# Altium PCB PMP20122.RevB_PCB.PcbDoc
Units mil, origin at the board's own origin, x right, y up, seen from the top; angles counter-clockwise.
Board outline 2960 x 1600 mil, 2 copper layers (Top Layer, Bottom Layer), stack 62 mil thick; 29 components, 14 nets, 63 pads, 28 vias.
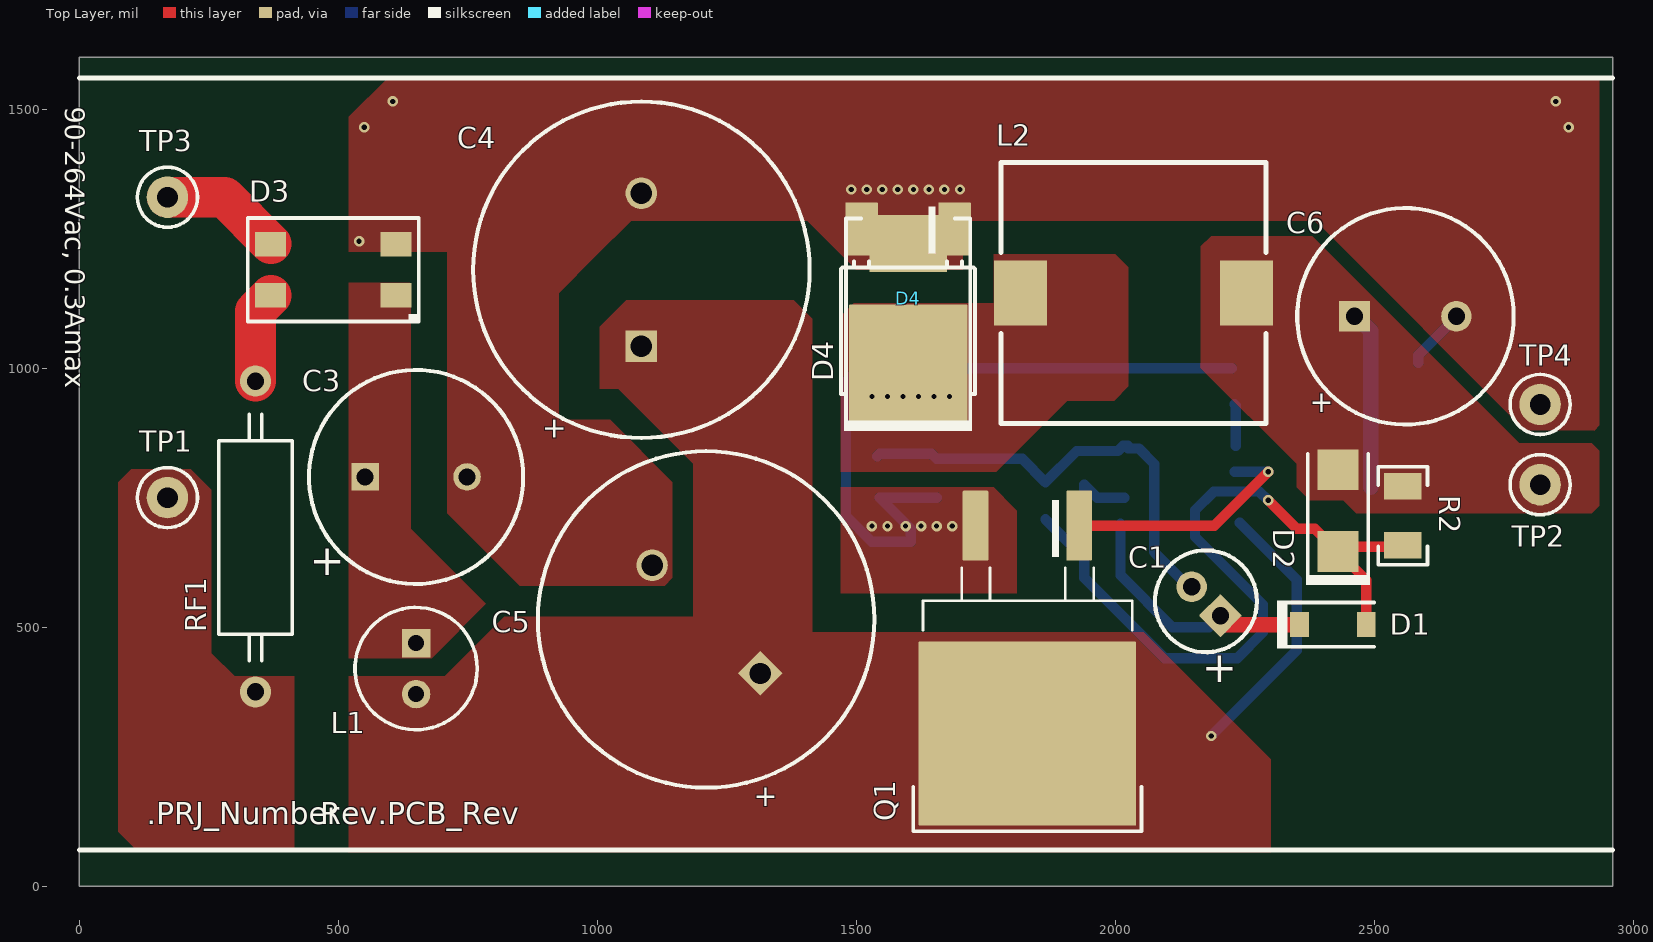
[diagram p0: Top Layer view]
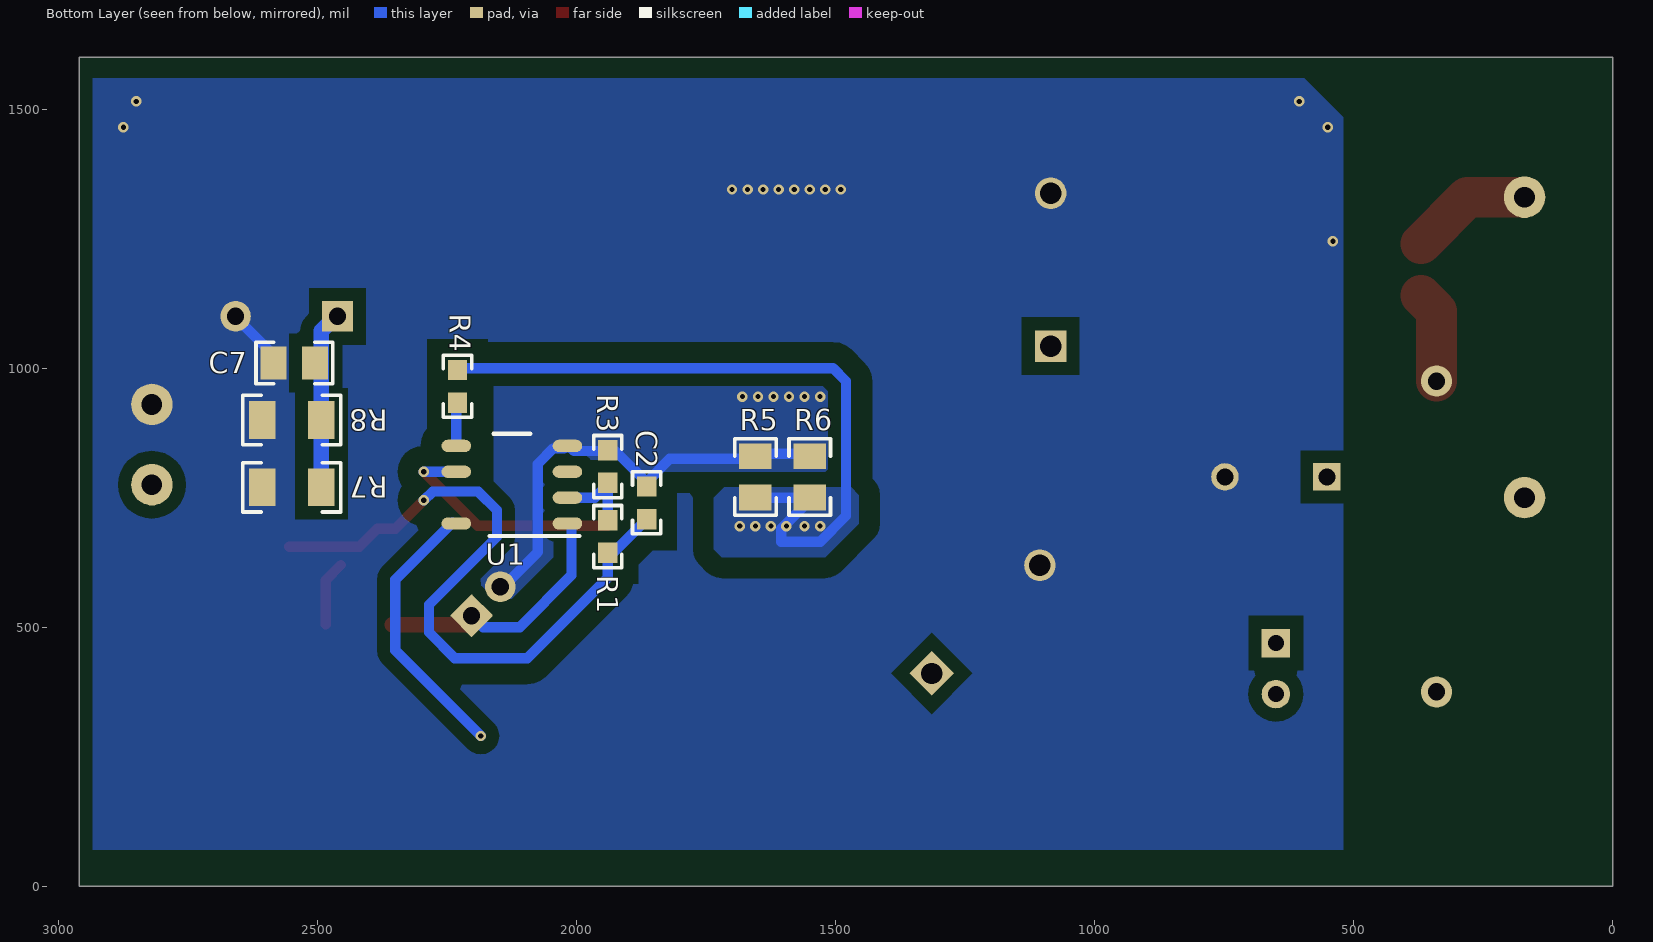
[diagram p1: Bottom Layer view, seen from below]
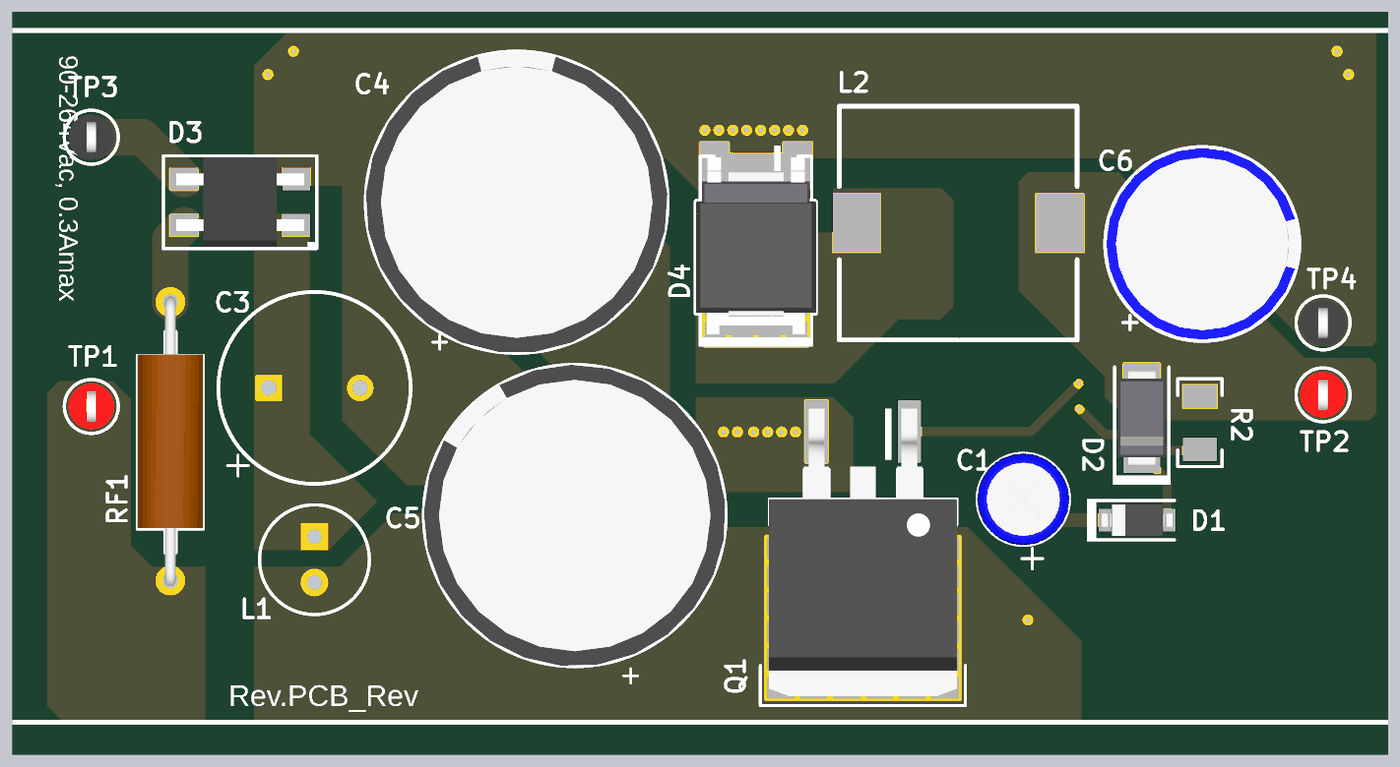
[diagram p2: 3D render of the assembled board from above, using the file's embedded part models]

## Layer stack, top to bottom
Top Solder: solder mask 0.4, Solder Resist, Dk 3.5
Top Layer: signal copper 1.4
Dielectric1: core 59.2, FR-4, Dk 4.8
Bottom Layer: signal copper 1.4
Bottom Solder: solder mask 0.4, Solder Resist, Dk 3.5

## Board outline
0,0 2960,0 2960,1600 0,1600

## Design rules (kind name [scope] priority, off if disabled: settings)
AcuteAngle [All] p1: minimum=4.50000000000000E+0001 checktracksonly=FALSE
AssemblyTestPointUsage [All] p1: valid=2
BoardOutlineClearance BoardOutlineClearance_MountingHoles [OnCopper and InComponentClass('Mounting Holes')] p1: gap=40
BoardOutlineClearance BoardOutlineClearance_Poly [OnCopper and IsPoly] p2: gap=25
BoardOutlineClearance [OnCopper and Not InComponentClass('Logo') and not InComponentClass('FiducialMark') and not InRegion(1000,500,4000,800) and not InPoly] p3: gap=75
Clearance Clearance_5 [InNetClass('SW') vs InNet('GND')] p1: gap=40
Clearance Clearance_4 [InNamedPolygon('TOP_LAYER_GND_P000')] p2: gap=60
Clearance Clearance_3 [InNamedPolygon('TOP_LAYER_GND_P000')] p3: gap=60
Clearance Clearance_2 [InNamedPolygon('TOP_LAYER_GND_P000')] p4: gap=10
Clearance Clearance_1 [InNetClass('HV') vs InNetClass('SW')] p5: gap=40
Clearance Clearance_Keepouts [((IsTrack Or IsArc) And Not InPoly) And IsFree and IsKeepOut vs ((IsTrack Or IsArc) And Not InPoly) And IsFree and IsKeepOut] p6: gap=0
Clearance Clearance_Poly [InPolygon] p7: gap=25
Clearance [All] p8: gap=7.87
ComponentClearance ComponentClearance_MountingHoles_FiducialMarks [InComponentClass('Mounting Holes') vs InComponentClass('FiducialMark')] p1: gap=50 collisioncheckmode=3 verticalgap=10 showdistances=FALSE
ComponentClearance ComponentClearance_Shunt [InComponentClass('Header') vs InComponentClass('Shunt')] p2: gap=0 collisioncheckmode=3 verticalgap=0 showdistances=FALSE
ComponentClearance ComponentClearance_Logo [InComponentClass('Logo')] p3: gap=50 collisioncheckmode=3 verticalgap=10 showdistances=FALSE
ComponentClearance ComponentClearance_ScrewToNut [(HasFootprint('NY PMS 440 0025 PH')) vs (HasFootprint('Keystone_1902C'))] p4: gap=5 collisioncheckmode=3 verticalgap=10 showdistances=FALSE
ComponentClearance ComponentClearance_MountingHoles [InComponentClass('Mounting Holes')] p5: gap=250 collisioncheckmode=3 verticalgap=100000 showdistances=FALSE
ComponentClearance ComponentClearance_SmallPassives [HasFootprint('0201*') or HasFootprint('0402*') or HasFootprint('0508') or HasFootprint('0603*') or HasFootprint('0612') or HasFootprint('0805*') or HasFootprint('0815*') or HasFootprint('0830*') or HasFootprint('1206*') or HasFootprint('1210*') or HasFootprint('1808*') or HasFootprint('1812*') or HasFootprint('1825*') or HasFootprint('2010*') or HasFootprint('2220*') or HasFootprint('2225*') or HasFootprint('2512*') or HasFootprint('2728*') or HasFootprint('3518*') vs HasFootprint('0201*') or HasFootprint('0402*') or HasFootprint('0508') or HasFootprint('0603*') or HasFootprint('0612') or HasFootprint('0805*') or HasFootprint('0815*') or HasFootprint('0830*') or HasFootprint('1206*') or HasFootprint('1210*') or HasFootprint('1808*') or HasFootprint('1812*') or HasFootprint('1825*') or HasFootprint('2010*') or HasFootprint('2220*') or HasFootprint('2225*') or HasFootprint('2512*') or HasFootprint('2728*') or HasFootprint('3518*')] p6: gap=14.96 collisioncheckmode=3 verticalgap=10 showdistances=FALSE
ComponentClearance ComponentClearance_THtoSMT [IsThruComponent vs IsSMTComponent] p7: gap=40 collisioncheckmode=3 verticalgap=30 showdistances=FALSE
ComponentClearance ComponentClearance_THtoTH [IsThruComponent vs IsThruComponent] p8: gap=30 collisioncheckmode=3 verticalgap=30 showdistances=FALSE
ComponentClearance [All] p9: gap=30 collisioncheckmode=3 verticalgap=10 showdistances=FALSE
DiffPairsRouting [All] p1: maxlimit=100 minlimit=10 mostfreqgap=10 toplayer_minwidth=15 toplayer_maxwidth=15 toplayer_prefwidth=15 bottomlayer_minwidth=15 bottomlayer_maxwidth=15 bottomlayer_prefwidth=15 maxuncoupledlength=1000
FabricationTestPointUsage TestPointUsage [All] p1: valid=2 allowmultiple=FALSE
FabricationTestpoint Testpoint [All] p1: side=3 testpointundercomponent=TRUE minsize=40 maxsize=100 preferedsize=60 minholesize=0 maxholesize=40 preferedholesize=32 testpointgrid=1 allowsidetop=TRUE allowsidebottom=TRUE usegrid=TRUE gridtolerance=0.01
FanoutControl Fanout_LCC [IsLCC] p1: bgadir=Out bgaviamode=Centered fanoutstyle=Auto fanoutdirection=Alternating viagrid=1 // Fanout_LCC (Default Rule)
FanoutControl Fanout_BGA [IsBGA] p2: bgadir=Out bgaviamode=Centered fanoutstyle=Auto fanoutdirection=Alternating viagrid=1 // Fanout_BGA (Default Rule)
FanoutControl Fanout_Default [All] p4: bgadir=Out bgaviamode=Centered fanoutstyle=Auto fanoutdirection=Alternating viagrid=1 // Fanout_Default (Default Rule)
FanoutControl Fanout_Small [(CompPinCount < 5)] p5: bgadir=Out bgaviamode=Centered fanoutstyle=Auto fanoutdirection=OutThenIn viagrid=1 // Fanout_Small (Default Rule)
Height [All] p1: minheight=0 maxheight=1500 prefheight=500
HoleSize [All] p1: absolutevalues=TRUE maxlimit=251 minlimit=7.87 maxpercent=80.000 minpercent=20.000
MinimumAnnularRing MinimumAnnularRing_ThermalPadVias [IsVia and InAnyComponent] p1: minimumring=5.91
MinimumAnnularRing [All] p2: minimumring=5
MinimumSolderMaskSliver MinimumSolderMaskSliver_Logo [InComponentClass('Logo') vs InComponentClass('Logo')] p1: minsoldermaskwidth=0.7
MinimumSolderMaskSliver [All] p2: minsoldermaskwidth=3.94
PlaneConnect [All] p1: planeconnectstyle=Relief reliefexpansion=10 reliefentries=4 reliefconductorwidth=10 reliefairgap=10
PolygonConnect PolygonConnect_19 [All vs IsNamedPolygon('BOTTOM_LAYER_GND_P022') Or  IsNamedPolygon('TOP_LAYER_NETC1_2_P003') Or  IsNamedPolygon('TOP_LAYER_NETRF1_2_P007') Or  IsNamedPolygon('Q1_3') Or  IsNamedPolygon('C1_2') Or  IsNamedPolygon('TOP_LAYER_NETC3_1_P004') Or  IsNamedPolygon('C6_1') Or  IsNamedPolygon('TOP_LAYER_GND_P024') Or  IsNamedPolygon('TOP_LAYER_NETC4_1_P001') Or  IsNamedPolygon('TOP_LAYER_NETQ1_3_P002')] p1: connectstyle=Direct reliefconductorwidth=10 reliefentries=4 polygonreliefangle="90 Angle" airgapwidth=10
PolygonConnect PolygonConnect_18 [All vs IsNamedPolygon('TOP_LAYER_GND_P009') Or  IsNamedPolygon('BOTTOM_LAYER_GND_P008') Or  IsNamedPolygon('TOP_LAYER_NETRF1_2_P007') Or  IsNamedPolygon('C6_1') Or  IsNamedPolygon('C1_2') Or  IsNamedPolygon('Q1_3') Or  IsNamedPolygon('TOP_LAYER_NETC3_1_P004') Or  IsNamedPolygon('TOP_LAYER_NETQ1_3_P002') Or  IsNamedPolygon('TOP_LAYER_NETC1_2_P003') Or  IsNamedPolygon('TOP_LAYER_NETC4_1_P001')] p2: connectstyle=Direct reliefconductorwidth=10 reliefentries=4 polygonreliefangle="90 Angle" airgapwidth=10
PolygonConnect PolygonConnect_17 [All vs IsNamedPolygon('TOP_LAYER_NETRF1_2_P007') Or  IsNamedPolygon('TOP_LAYER_NETC3_1_P004') Or  IsNamedPolygon('TOP_LAYER_NETC1_2_P003') Or  IsNamedPolygon('TOP_LAYER_GND_P009') Or  IsNamedPolygon('Q1_3') Or  IsNamedPolygon('TOP_LAYER_NETC2_1_P006') Or  IsNamedPolygon('BOTTOM_LAYER_GND_P008') Or  IsNamedPolygon('TOP_LAYER_NETC6_1_P005') Or  IsNamedPolygon('C1_2') Or  IsNamedPolygon('TOP_LAYER_NETQ1_3_P002') Or  IsNamedPolygon('TOP_LAYER_NETC4_1_P001')] p3: connectstyle=Direct reliefconductorwidth=10 reliefentries=4 polygonreliefangle="90 Angle" airgapwidth=10
PolygonConnect PolygonConnect_16 [All vs IsNamedPolygon('BOTTOM_LAYER_GND_P008') Or  IsNamedPolygon('TOP_LAYER_NETC6_1_P005') Or  IsNamedPolygon('TOP_LAYER_GND_P009') Or  IsNamedPolygon('TOP_LAYER_NETRF1_2_P007') Or  IsNamedPolygon('TOP_LAYER_NETC2_1_P006') Or  IsNamedPolygon('TOP_LAYER_NETC1_2_P003') Or  IsNamedPolygon('TOP_LAYER_NETC3_1_P004') Or  IsNamedPolygon('Q1_3') Or  IsNamedPolygon('TOP_LAYER_NETQ1_3_P002') Or  IsNamedPolygon('TOP_LAYER_NETC4_1_P001')] p4: connectstyle=Direct reliefconductorwidth=10 reliefentries=4 polygonreliefangle="90 Angle" airgapwidth=10
PolygonConnect PolygonConnect_15 [All vs IsNamedPolygon('TOP_LAYER_NETC1_2_P006') Or  IsNamedPolygon('TOP_LAYER_NETC3_1_P008') Or  IsNamedPolygon('TOP_LAYER_NETC6_1_P012') Or  IsNamedPolygon('BOTTOM_LAYER_GND_P018') Or  IsNamedPolygon('TOP_LAYER_GND_P000') Or  IsNamedPolygon('TOP_LAYER_NETC4_1_P002') Or  IsNamedPolygon('TOP_LAYER_NETC2_1_P014') Or  IsNamedPolygon('TOP_LAYER_NETQ1_3_P004') Or  IsNamedPolygon('TOP_LAYER_NETRF1_2_P007') Or  IsNamedPolygon('Q1_3')] p5: connectstyle=Direct reliefconductorwidth=10 reliefentries=4 polygonreliefangle="90 Angle" airgapwidth=10
PolygonConnect PolygonConnect_14 [All vs IsNamedPolygon('BOTTOM_LAYER_GND_P018')] p6: connectstyle=Direct reliefconductorwidth=10 reliefentries=4 polygonreliefangle="90 Angle" airgapwidth=10
PolygonConnect PolygonConnect_13 [All vs IsNamedPolygon('TOP_LAYER_NETC2_1_P014')] p7: connectstyle=Direct reliefconductorwidth=10 reliefentries=4 polygonreliefangle="90 Angle" airgapwidth=10
PolygonConnect PolygonConnect_12 [All vs IsNamedPolygon('TOP_LAYER_NETC6_1_P012')] p8: connectstyle=Direct reliefconductorwidth=10 reliefentries=4 polygonreliefangle="90 Angle" airgapwidth=10
PolygonConnect PolygonConnect_11 [All vs IsNamedPolygon('TOP_LAYER_NETC6_1_P012')] p9: connectstyle=Direct reliefconductorwidth=10 reliefentries=4 polygonreliefangle="90 Angle" airgapwidth=10
PolygonConnect PolygonConnect_10 [All vs IsNamedPolygon('TOP_LAYER_NETRF1_2_P007')] p10: connectstyle=Direct reliefconductorwidth=10 reliefentries=4 polygonreliefangle="90 Angle" airgapwidth=10
PolygonConnect PolygonConnect_9 [All vs IsNamedPolygon('TOP_LAYER_GND_P000')] p11: connectstyle=Direct reliefconductorwidth=10 reliefentries=4 polygonreliefangle="90 Angle" airgapwidth=10
PolygonConnect PolygonConnect_8 [All vs IsNamedPolygon('TOP_LAYER_NETC3_1_P008')] p12: connectstyle=Direct reliefconductorwidth=10 reliefentries=4 polygonreliefangle="90 Angle" airgapwidth=10
PolygonConnect PolygonConnect_7 [All vs IsNamedPolygon('TOP_LAYER_NETC3_1_P008')] p13: connectstyle=Direct reliefconductorwidth=10 reliefentries=4 polygonreliefangle="90 Angle" airgapwidth=10
PolygonConnect PolygonConnect_6 [All vs IsNamedPolygon('TOP_LAYER_NETC1_2_P006')] p14: connectstyle=Direct reliefconductorwidth=10 reliefentries=4 polygonreliefangle="90 Angle" airgapwidth=10
PolygonConnect PolygonConnect_5 [All vs IsNamedPolygon('TOP_LAYER_NETQ1_3_P004')] p15: connectstyle=Direct reliefconductorwidth=10 reliefentries=4 polygonreliefangle="90 Angle" airgapwidth=10
PolygonConnect PolygonConnect_4 [All vs IsNamedPolygon('TOP_LAYER_NETC4_1_P002')] p16: connectstyle=Direct reliefconductorwidth=10 reliefentries=4 polygonreliefangle="90 Angle" airgapwidth=10
PolygonConnect PolygonConnect_3 [All vs IsNamedPolygon('TOP_LAYER_NETC4_1_P002')] p17: connectstyle=Direct reliefconductorwidth=10 reliefentries=4 polygonreliefangle="90 Angle" airgapwidth=10
PolygonConnect PolygonConnect_2 [All vs IsNamedPolygon('TOP_LAYER_NETC4_1_P002')] p18: connectstyle=Direct reliefconductorwidth=10 reliefentries=4 polygonreliefangle="90 Angle" airgapwidth=10
PolygonConnect PolygonConnect_1 [All vs IsNamedPolygon('TOP_LAYER_GND_P000')] p19: connectstyle=Direct reliefconductorwidth=10 reliefentries=4 polygonreliefangle="90 Angle" airgapwidth=10
PolygonConnect [All] p20: connectstyle=Relief reliefconductorwidth=10 reliefentries=4 polygonreliefangle="90 Angle" airgapwidth=10
RoutingVias ThermalPadVias [IsVia and InAnyComponent] p1: holewidth=7.87 width=19.68 viastyle="Through Hole" minholewidth=7.87 minwidth=19.68 maxholewidth=12.99 maxwidth=23.62
RoutingVias [All] p2: holewidth=16 width=34 viastyle="Through Hole" minholewidth=7.87 minwidth=20 maxholewidth=40 maxwidth=65
SMDToCorner [All] p1: distance=30000
SilkToBoardRegionClearance [Not ((IsComment or IsDesignator) And (Hide <> 'False')) and not InRegion(1000,500,4000,800)] p1:
SilkToSilkClearance SilkToSilkClearance_Pb-FreeLogo [(HasFootprint('Pb-Free_Overlay_Medium') OR HasFootprint('Pb-Free_Overlay_Small')) vs (HasFootprint('Pb-Free_Overlay_Medium') OR HasFootprint('Pb-Free_Overlay_Small'))] p1: silktosilkclearance=0
SilkToSilkClearance [All] p2: silktosilkclearance=4
SilkToSolderMaskClearance SilkToComponentPadClearance [IsPad and InAnycomponent] p1: minsilkscreentomaskgap=5 clearancetoexposedcopper=TRUE
SilkToSolderMaskClearance "Silk to Solder Mask Opening" [All] p2: minsilkscreentomaskgap=4 clearancetoexposedcopper=FALSE
SolderMaskExpansion [All] p1: expansion=1.97
Width [All] p1: maxlimit=100 minlimit=10 preferedwidth=10 minimp=50.000000 maximp=50.000000 favimp=50.000000
14 further rules are at their usual default settings.

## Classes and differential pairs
component class PMP20122_RevB: C1 C6 C7 D1 D2 D3 L1 L2 R1 R2 R3 R4 R5 R6 R7 R8 RF1 TP1 TP2 TP3 TP4 U1
net class HV: NetC3_1 NetC4_1 NetD3_3 NetD3_4 NetRF1_2
net class SW: NetC1_1 NetC1_2 NetC2_1 NetQ1_1 NetQ1_3 NetR1_2 NetR4_2

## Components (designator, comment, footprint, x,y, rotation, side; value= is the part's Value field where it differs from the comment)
C1 "UVR1V100MDD1TA" CAPPR2-5x11 2175,550 r135 top
C2 "06035A220JAT2A" 0603 1865,740 r90 bottom
C3 "400AX6R8M8x11" CS_1000x1600 650,790 r0 top
C4 "EEU-ED2G150" SMG_1600x3550#1 1085,1190 r90 top
C5 "EEU-ED2G150" SMG_1600x3550#2 1210,515 r90 top
C6 "16ZL680MEFC10X16" ZL_1000x1600 2560,1100 r0 top
C7 "08055C105KAT2A" 0805_HV 2545,1010 r0 bottom
D1 "1N4148W-7-F" SOD-123 2420,505 r0 top
D2 "ES1J-TP" SMA 2430,725 r90 top
D3 "RH06-T" MiniDIP 490,1190 r180 top
D4 "ES3J" SMC 1600,1100 r90 top
D4 "Comment" DPAK 1600,1135 r270 top
L1 "PartNumber" IND_WE-TI_XS 650,420 r270 top
L2 "SLF12575T-470M2R7-PF" SLF12575 2035,1145 r0 top
Q1 "STD3NK60ZD" DDPAK 1420,575 r270 top
R1 "CRCW060337K4FKEA" 0603 1940,675 r90 bottom
R2 "CRCW1206432KFKEA" 1206 2555,715 r270 top
R3 "CRCW060318K7FKEA" 0603 1940,810 r270 bottom
R4 "CRCW0603301RFKEA" 0603 2230,965 r270 bottom
R5 "CRM0805-FX-R510ELF" 0805_HV 1655,790 r90 bottom
R6 "ERJ-6RQFR68V" 0805_HV 1550,790 r90 bottom
R7 "CRCW12065K10JNEA" 1206 2550,770 r180 bottom
R8 "CRCW12065K10JNEA" 1206 2550,900 r180 bottom
RF1 "FKN1WSJR-52-4R7" RESAD1524W55L900D150 340,675 r270 top
TP1 "5000" Keystone5000 170,750 r0 top
TP2 "5000" Keystone5000 2820,775 r0 top
TP3 "5001" Keystone5001 170,1330 r0 top
TP4 "5001" Keystone5001 2820,930 r0 top
U1 "UCC28710D" D0007A_N 2125,775 r0 bottom

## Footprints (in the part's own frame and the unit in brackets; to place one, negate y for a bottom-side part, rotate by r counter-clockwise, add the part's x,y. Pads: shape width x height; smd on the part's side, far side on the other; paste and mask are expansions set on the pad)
0603 [mm] "0603 from SM-752 data"
  rect 1x0.95 smd: 1(-0.8,0) 2(0.8,0)
  silkscreen extent -1.52,-0.69 1.52,0.69, body extent -0.87,-0.47 0.87,0.47, height 1
0805_HV [mil] "0805 with 30mil clearance between pads"
  rect 50x63 smd: 1(-40,0) 2(40,0)
  silkscreen extent -74,-40 74,40, body extent -43,-29 43,29, height 57
1206 [mm] "1206 from SM-752 data"
  rect 1.3x1.85 smd: 1(-1.45,0) 2(1.45,0)
  silkscreen extent -2.4,-1.21 2.4,1.21, body extent -1.7,-0.9 1.7,0.9, height 1.35
CAPPR2-5x11 [mm] "Capacitor, Electrolytic, Radial; Body 5 x 11 mm (Dia.xH typ); Pin Spacing 2 mm (typ)"
  rrect7% 1.5x1.5 hole 0.85: 1(-1,0)
  round 1.5 hole 0.85: 2(1,0)
  silkscreen extent -2.5,-2.5 2.5,2.5, body extent -2.53,-2.53 2.53,2.52, height 11.29
CS_1000x1600 [mm] "TH, 2-Leads, Dia 10mm, Lead Spacing 5mm"
  rect 1.35x1.35 hole 0.85: 1(-2.5,0)
  round 1.35 hole 0.85: 2(2.5,0)
  silkscreen extent -5.25,-5.25 5.25,5.25, body extent -5.21,-5.24 5.26,5.24, height 17.69
D0007A_N [mm] "SOIC, 7-Leads, Body 4.9x3.9mm, Pitch 1.27mm, IPC Medium Density"
  oval 1.45x0.6 smd: 1(-2.725,1.905) 2(-2.725,0.635) 3(-2.725,-0.635) 4(-2.725,-1.905) 5(2.725,-1.905) 6(2.725,-0.635) 8(2.725,1.905)
  silkscreen extent -3.32,-2.5 1.1,2.52, body extent -3.01,-2.45 3.01,2.45, height 1.75
DDPAK [mil] "D2-PAK, 3-Pads, Body 9.7x10.4mm (max), TO-263AB, using Vishay Silionix recommended pad sizes"
  rrect8% 135x49.49 smd: 1(-121.06,510) 3(-121.06,310)
  rrect1% 355x420 smd paste-181.1: 4(280.51,410)
  silkscreen extent -170,190 469,630, body extent -170,208 449,612, height 180
DPAK [mm] "D-PAK, 3-Pads, Body 6.22x6.73mm (max), TO-252AA using nominal STEP model"
  rrect6% 2.6x1.6 smd: 1(-3.4,2.28) 3(-3.4,-2.28)
  rrect2% 6.2x5.8 smd paste-2.9: 4(3.4,0)
  silkscreen extent -4.5,-3.3 4.7,3.28, body extent -3.86,-3.29 5.84,3.29, height 2.48
IND_WE-TI_XS [mm] "Wurth WE-TI 5075"
  rect 1.4x1.4 hole 0.787: 1(-1.25,0)
  round 1.4 hole 0.787: 2(1.25,0)
  silkscreen extent -3,-3 3,3, body extent -3,-3 3,3, height 8.5
Keystone5000 [mil] "For Keystone 500x miniature loop terminals"
  round 80 hole 40: 1(0,0)
  silkscreen extent -58,-58 58,58, body extent -49,-49 49,49, height 182
Keystone5001 [mil] "For Keystone 500x miniature loop terminals"
  round 80 hole 40: 1(0,0)
  silkscreen extent -58,-58 58,58, body extent -49,-49 49,49, height 182
MiniDIP [mm] "Land pattern created based on STEP model."
  rect 1.52x1.2 smd: 1(-3.075,1.25) 2(-3.075,-1.25) 3(3.075,-1.25) 4(3.075,1.25)
  silkscreen extent -4.19,-2.54 4.19,2.54, body extent -3.5,-2.45 3.5,2.45, height 2.75
RESAD1524W55L900D150 [mil]
  round 60 hole 33.46: 1(-300,0) 2(300,0)
  silkscreen extent -236,-71 240,71, body extent -312,-71 312,71, height 141
SLF12575 [mm] "TDK recommended land pattern"
  rect 2.6x3.2 smd: 1(-5.55,0) 2(5.55,0)
  silkscreen extent -6.5,-6.4 6.5,6.4, body extent -6.4,-6.4 6.4,6.4, height 7.85
SMA [mm] "Molded Diode, 2-Leads, Body 4.3x2.6mm, IPC Medium Density, based on OnSemi component dimensions and land pattern"
  rect 2x2 smd: 1(-2,0) 2(2,0)
  silkscreen extent -3.66,-1.57 2.79,1.57, body extent -2.6,-1.3 2.6,1.3, height 2.42
SMC [mil] "Molded Diode, 2-Leads, Body 6.9x5.8mm, IPC Medium Density, based on OnSemi component dimensions and land patterns"
  rect 110x150 smd: 1(-140.49,0) 2(140.49,0)
  silkscreen extent -221,-124 189,123, body extent -156,-116 156,116, height 91
SMG_1600x3550#1 [mm] "TH, 2-Leads, Dia 16mm, Pin Spacing 7.5mm"
  rect 1.55x1.55 hole 1.05: 1(-3.75,0)
  round 1.55 hole 1.05: 2(3.75,0)
  silkscreen extent -8.25,-8.25 8.25,8.25, body extent -8.25,-8.25 8.26,8.25, height 37.01
SMG_1600x3550#2 [mm] "TH, 2-Leads, Dia 16mm, Pin Spacing 7.5mm"
  rect 1.55x1.55 hole 1.05 rot 45: 1(-2.652,-2.652)
  round 1.55 hole 1.05: 2(2.652,2.652)
  silkscreen extent -8.25,-8.25 8.25,8.25, body extent -11.67,-11.67 11.67,11.67, height 37.01
SOD-123 [mm] "On Semi recommended land pattern"
  rect 0.915x1.22 smd: 1(-1.637,0) 2(1.637,0)
  silkscreen extent -2.74,-1.17 2.03,1.17, body extent -1.93,-0.9 1.93,0.9, height 1.35
ZL_1000x1600 [mm] "RUBYCON"
  rect 1.5x1.5 hole 0.85: 1(-2.5,0)
  round 1.5 hole 0.85: 2(2.5,0)
  silkscreen extent -5.3,-5.31 5.31,5.31, body extent -5.2,-5.23 5.25,5.25, height 17.51

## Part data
C1: "CAP, AL, 10uF, 35V, +/-20%, TH"
C2: "CAP, CERM, 22pF, 50V, +/-5%, C0G/NP0, 0603"
C3: "CAP, AL, 6.8uF, 400V, +/-20%, TH"
C4 C5: "CAP, AL, 15 µF, 400 V, +/- 20%, TH"
C6: "CAP, AL, 680 µF, 16 V, +/- 20%, 0.038 ohm, TH"
C7: "CAP, CERM, 1uF, 50V, +/-10%, X7R, 0805"
D1: "Diode, Ultrafast, 100V, 0.15A, SOD-123"
D2: library part ES1D-13-F, "DIODE FAST REC 600V 1A DO214AC"
D3: "Diode, Switching-Bridge, 600V, 0.5A, MiniDIP"
D4: "Diode, Fast Rectifier, 600 V, 3 A, SMC"
L1: library part 7447462102, "Inductor, Unshielded Drum Core, Ferrite, 1mH, 0.25A, 4.38 ohm, TH"
L2: "Inductor, Shielded, Ferrite, 47 µH, 3 A, 0.0528 ohm, SMD"
Q1: library part STD13NM60N, "MOSFET N-CH 600V 2.4A DPAK"
R1: "RES, 37.4 k, 1%, 0.1 W, 0603"
R2: "RES, 432k ohm, 1%, 0.25W, 1206"
R3: "RES, 18.7k ohm, 1%, 0.1W, 0603"
R4: "RES, 301 ohm, 1%, 0.1W, 0603"
R5: "RES, 0.51, 1%, 0.25 W, 0805"
R6: "RES, 0.68, 1%, 0.125 W, 0805"
R7 R8: "RES, 5.1k ohm, 5%, 0.25W, 1206"
RF1: "RES, 4.7 ohm, 5%, 1W, Fusible, TH"
TP1 TP2: "Test Point, Miniature, Red, TH"
TP3 TP4: "Test Point, TH, Miniature, Black"
U1: "Constant-Voltage, Constant-Current Controller With Primary-Side Regulation, D0007A"

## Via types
v1: diameter 20, hole 10, Top Layer to Bottom Layer, 28 vias

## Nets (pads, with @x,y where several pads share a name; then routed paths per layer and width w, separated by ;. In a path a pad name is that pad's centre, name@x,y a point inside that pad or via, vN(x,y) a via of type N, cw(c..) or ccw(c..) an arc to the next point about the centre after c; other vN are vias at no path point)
GND: C3.2 C4.2 C5.2 C6.2 C7.2 D3.2 D4.1@1689.76,1268.86 D4.2 D4.3 R7.1 R8.1 TP4.1 | length 121.1
  Bottom Layer w20: C7.2 2585,1025 C6.2@2660,1100
  other v1: 540,1245 1490,1345 1520,1345 1550,1345 1580,1345 1610,1345 1640,1345 1670,1345 1700,1345 550,1465 2875,1465 605,1515 2850,1515
NetC1_1: C1.1 D1.1 U1.1 | length 490.2
  Top Layer w30: C1.1@2205,505 D1.1
  Bottom Layer w20: U1.1@2010,700 2010,600 2110,500 2180,500 C1.1@2200,520
NetC1_2: C1.2 C2.2 D4.1@1600,959.51 D4.4 L2.1 R3.1 R5.2 R6.2 U1.4 | length 871.4
  Bottom Layer w20: R6.2@1540,830 1545,835 1645,835 R5.2@1655,825 ; R5.2@1660,825 1820,825 1865,780 1925,840 2005,840 U1.4@2015,850 ; U1.4@2020,850 U1.4@2024.13,850 ; U1.4@2025,845 2045,845 2075,815 2075,645 C1.2@2131.45,588.55 ; C1.2@2140,575 2139.33,576.06 C1.2@2131.45,588.55 ; C1.2@2142.16,577.84 C1.2@2131.45,588.55
  other v1: 1530,945 1560,945 1590,945 1620,945 1650,945 1680,945
NetC2_1: C2.1 D1.2 D2.1 R1.1 R2.2 | length 1445.9
  Top Layer w20: v1(2295,745) 2350,690 2385,690 2420,655 R2.2@2555,655 ; D2.1@2455,620 2484.47,590.53 D1.2
  Bottom Layer w20: C2.1 R1.1@1928.5,645 ; R1.1 1940,595 2095,440 2235,440 2285,490 2285,543.14 2153.74,674.4 2153.74,725.6 2189.95,761.81 2278.19,761.81 v1(2295,745)
NetC3_1: C3.1 D3.1 L1.1
NetC4_1: C4.1 C5.1 L1.2 Q1.4 U1.8 | length 525.7
  Bottom Layer w20: v1(2185,290) 2350,455 2350,591.81 U1.8@2240,701.81
NetC6_1: C6.1 C7.1 D2.2 L2.2 R2.1 R7.2 R8.2 TP2.1 | length 361.8
  Bottom Layer w20: C6.1@2461.57,1103.43 C6.1@2461.57,1116.57
  Bottom Layer w30: C6.1@2460,1105 2461.57,1103.43 2492.91,1072.09 R8.2 R7.2
NetD3_3: D3.3 TP3.1 | length 237.3
  Top Layer w78.74: TP3.1 280,1330 D3.3@370,1240
NetD3_4: D3.4 RF1.1 | length 177.4
  Top Layer w78.74: RF1.1 340,1110 D3.4@370,1140
NetQ1_1: Q1.1 U1.6 | length 463.1
  Top Layer w20: Q1.1@1940,696.06 2191.06,696.06 v1(2295,800)
  Bottom Layer w20: U1.6@2230,800 U1.6 v1(2295,800)
NetQ1_3: Q1.3 R4.1 R5.1 R6.1 | length 1375.9
  Bottom Layer w20: 1505,1000 1480,975 1480,715 1530,665 1605,665 1605,690 1545,750 R5.1 ; 1510,1000 R4.1@2225,1000
  other v1: 1530,695 1560,695 1595,695 1625,695 1655,695 1685,695
NetR1_2: R1.2 R3.2 U1.2 | length 158.1
  Bottom Layer w20: R1.2@1940,705 R1.2 1940,775 1965,750 U1.2
NetR4_2: R4.2 U1.5 | length 80.9
  Bottom Layer w20: R4.2@2230,930 2232.28,927.72 U1.5
NetRF1_2: RF1.2 TP1.1
pads on no net: U1.3

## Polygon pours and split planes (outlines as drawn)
NetRF1_2 on Top Layer "TOP_LAYER_NETRF1_2_P007" (solid, remove dead copper, pour order 7): 75,780 100,805 215,805 240,780 255,765 255,450 300,405 415,405 415,70 110,70 75,105
NetC3_1 on Top Layer "TOP_LAYER_NETC3_1_P004" (solid, remove dead copper, pour order 4): 645,1165 640,1160 640,700 640,690 785,545 680,440 570,440 520,440 520,1165
NetC1_2 on Top Layer "TOP_LAYER_NETC1_2_P003" (solid, remove dead copper, pour order 3): 1495,1125 1680,1125 1765,1125 1765,1220 2000,1220 2025,1195 2025,965 1997.5,937.5 1907.5,937.5 1770,800 1470,800 1470,1100
NetQ1_3 on Top Layer "TOP_LAYER_NETQ1_3_P002" (solid, remove dead copper, pour order 2): 1470,770 1765,770 1805,730 1810,725 1810,565 1470,565
NetC4_1 on Top Layer "TOP_LAYER_NETC4_1_P001" (solid, remove dead copper, pour order 1): 1005,1080 1056.2,1131.2 1378.8,1131.2 1415,1095 1415,490 2055,490 2192.5,352.5 2300,245 2300,65 520,65 520,405 700,405 705,405 820,520 1185,520 1185,815 1040,960 1005,960
GND on Top Layer "TOP_LAYER_GND_P024" (solid, remove dead copper, pour order 24): 520,1485 520,1225 710,1225 710,720 850,580 1130,580 1145,595 1145,780 1025,900 925,900 925,1145 995,1215 1065,1285 1405.25,1285 1500.25,1190 1705,1190 1705,1285 1788.32,1285 2270,1285 2385,1285 2630,1040 2755,915 2795,875 2920,875 2935,890 2935,1560 595,1560
NetC6_1 on Top Layer "C6_1" (solid, remove dead copper, pour order 9): 2185,1255 2165,1235 2165,1000 2350,815 2350,775 2350,770 2370,750 2375,745 2440,745 2450,735 2465,720 2855,720 2920,720 2935,735 2935,785 2935,840 2920,855 2840,855 2780,855 2380,1255
GND on Bottom Layer "BOTTOM_LAYER_GND_P022" (solid, remove dead copper, pour order 22): 519.8,1484.8 595,1560 2935,1560 2935,70 519.8,70
NetQ1_3 on Bottom Layer "Q1_3" (solid, remove dead copper, pour order 0): 1525,770 1480,770 1470,770 1455,755 1455,740 1455,700 1520,635 1555,635 1720,635 1735,650 1735,750 1715,770
NetC1_2 on Bottom Layer "C1_2" (solid, remove dead copper, pour order 8): 1520,800 1505,815 1505,820 1505,965 1520,980 1645,980 2150,980 2160,970 2160,875 2160,665 2205,620 2205,555 2175,555 2125,555 1880,800

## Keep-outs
Keep-Out Layer:
  text ".Layer_Name" at 577,-848.49 h60

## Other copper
Top Layer:
  text ".Layer_Name" at 577,-848.49 h60
Bottom Layer:
  text ".Layer_Name" at 577,-848.49 h60

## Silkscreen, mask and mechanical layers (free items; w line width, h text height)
Top Overlay:
  lines w10: 0,70 2960,70 ; 0,1560 2960,1560
  text "90-264Vac, 0.3Amax" at -40,1505 h65 r270
  text ".PRJ_Number" at 130,105 h72.83
  text "Rev.PCB_Rev" at 465,105 h72.83
  text ".Layer_Name" at 577,-848.49 h60
Bottom Overlay:
  text ".Layer_Name" at 577,-848.49 h60
Top Paste:
  text ".Layer_Name" at 577,-848.49 h60
Bottom Paste:
  text ".Layer_Name" at 577,-848.49 h60
Top Solder:
  text ".Layer_Name" at 577,-848.49 h60
  text ".Layer_Name" at 577,-848.49 h60
Bottom Solder:
  text ".Layer_Name" at 577,-848.49 h60
Drill Guide:
  text ".Layer_Name" at 577,-848.49 h60
M1 Board Outline:
  the board outline again, w7
  text ".Layer_Name" at 577,-848.49 h60
M2 Board Dimensions:
  rectangle: 0,-265 125,-140
  rectangle: 125,-390 500,-265
  lines w7: 0,-265 1000,-265 ; 125,-390 125,-140 ; 250,-390 250,-140 ; 500,-390 500,-140 ; 750,-390 750,-140 ; 0,-390 1000,-390 1000,-140 0,-140 0,-390
  text ".Layer_Name" at 577,-848.49 h60
M3 3D STEP Top:
  text ".Layer_Name" at 577,-848.49 h60
M4 3D STEP Bottom:
  text ".Layer_Name" at 577,-848.49 h60
M5 Assembly Top:
  lines w10: -292,-920.17 6308,-920.17 ; -292,-716.83 6310,-716.83 ; -292,-513.5 -292,-1123.5 3713,-1123.5 6310,-1123.5 6310,-513.5 -291.5,-513.5 -291.5,-1123.5 1284,-1123.5 ; 2173,-1123.5 2173,-513.5 ; 3440,-716.83 3440,-513.5 ; 4280,-716.83 4280,-513.5 ; 4902,-1130 4902,-927.17
  text "COMPONENTS MARKED 'DNP' SHOULD NOT BE POPULATED." at 1153.5,-308.5 h60
  text "ASSEMBLY VARIANT:" at 1153,-424 h60
  text ".VariantName" at 2189,-424 h60
  text "PCB VIEWED FROM TOP SIDE" at -228.5,-645.67 h60
  text "BOARD #:" at 2248,-645.67 h60
  text ".PRJ_Number" at 2793.5,-645.67 h60
  text "REV:" at 3638,-645.67 h60
  text ".PCB_Rev" at 3929.5,-645.67 h60
  text "SVN REV:" at 4476,-645.67 h60
  text ".VersionControl_RevNumber" at 4982,-645.67 h60
  text "TID #:" at 2248,-849 h60
  text ".TID" at 2793.5,-849 h60
  text "PLOT NAME =" at -228.5,-1054.34 h60
  text ".plot_File_Name" at 577,-1054.34 h60
  text "GENERATED    :" at 2250,-1054.34 h60
  text ".Print_Date" at 3119.5,-1054.34 h60
  text ".Print_Time" at 3848.5,-1054.34 h60
  text "TEXAS INSTRUMENTS" at 5113,-1054.34 h60
M6 Assembly Bottom:
  lines w10: -292.5,-717.33 6309.5,-717.33 ; -290.5,-920.67 6309.5,-920.67 ; 1115.5,-1130.5 1115.5,-927.67 ; 1737.5,-717.33 1737.5,-514 ; 2577.5,-717.33 2577.5,-514 ; 3844.5,-1124 3844.5,-514 ; 4733.5,-1124 6309,-1124 6309,-514 -292.5,-514 -292.5,-1124 2304.5,-1124 6309.5,-1124 6309.5,-514
  text "COMPONENTS MARKED 'DNP' SHOULD NOT BE POPULATED." at 6102,-308 h60
  text ".VariantName" at 5058,-424 h60
  text "ASSEMBLY VARIANT:" at 6097,-424 h60
  text ".VersionControl_RevNumber" at 1035.5,-646.17 h60
  text "SVN REV:" at 1541.5,-646.17 h60
  text ".PCB_Rev" at 2088,-646.17 h60
  text "REV:" at 2379.5,-646.17 h60
  text ".PRJ_Number" at 3224,-646.17 h60
  text "BOARD #:" at 3769.5,-646.17 h60
  text "PCB VIEWED FROM BOTTOM SIDE" at 6246,-646.17 h60
  text ".TID" at 3224,-849.5 h60
  text "TID #:" at 3769.5,-849.5 h60
  text "TEXAS INSTRUMENTS" at 904.5,-1054.84 h60
  text ".Print_Time" at 2169,-1054.84 h60
  text ".Print_Date" at 2898,-1054.84 h60
  text "GENERATED    :" at 3767.5,-1054.84 h60
  text ".plot_File_Name" at 5440.5,-1054.84 h60
  text "PLOT NAME =" at 6246,-1054.84 h60
M9 Title Sheet:
  drawing of 57 lines, arcs and shapes, not listed
  text "1" at 739.84,8046.5 h70
  text "2" at 3235.5,8046.5 h70
  text "3" at 5724.84,8046.5 h70
  text "4" at 8231.51,8046.5 h70
  text "5" at 10730.5,8046.5 h70
  text "6" at 13235.5,8046.5 h70
  text "A" at -416.5,6903.5 h70
  text "A" at 14383.5,6903.5 h70
  text "B" at -416.5,4523.5 h70
  text "B" at 14383.5,4523.5 h70
  text "C" at -416.5,2148.5 h70
  text "C" at 14383.5,2148.5 h70
  text "PROJECT TITLE:" at 11343.5,287.5 h45
  text ".PRJ_Title" at 11393.5,154.17 h70
  text "DESIGNED FOR:" at 11343.5,-13.5 h45
  text ".PRJ_Customer" at 11393.5,-153.5 h70
  text "D" at -416.5,-221.5 h70
  text "D" at 14383.5,-221.5 h70
  text "FILE NAME:" at 11343.5,-313.5 h45
  text ".PCB_File_Name_No_Path" at 11393.5,-433.5 h70
  text "Texas Instruments (TI) and/or its licensors do not warrant the accuracy or completeness of this specification" at 6374,-595.34 h45
  text "ENGINEER:" at 11343.5,-603.5 h45
  text "LAYOUT BY:" at 12848.5,-603.5 h45
  text "or any information contained therein. TI and/or its licensors do not warrant that this design will meet" at 6329.01,-708 h45
  text ".PRJ_Engineer" at 11393.5,-758.49 h70
  text ".PCB_Layout" at 12899,-758.49 h70
  text "the specifications, will be suitable for your application or fit for any particular purpose, or will operate in" at 6329.01,-820.67 h45
  text ".Layer_Name" at 577,-848.49 h60
  text "ALTIUM DESIGNER VERSION:" at 12848.5,-913.5 h45
  text "an implementation. TI and/or its licensors do not warrant that the design is production worthy. You should" at 6329.01,-933.33 h45
  text "completely validate and test your design implementation to confirm the system functionality for your application." at 6374,-1046 h45
  text ".print_Scale" at 11393.5,-1046.83 h70
  text ".Application_BuildNumber" at 12899,-1046.83 h70
  text "1" at 739.84,-1253.5 h70
  text "2" at 3235.5,-1253.5 h70
  text "3" at 5724.84,-1253.5 h70
  text "4" at 8231.51,-1253.5 h70
  text "5" at 10730.5,-1253.5 h70
  text "6" at 13235.5,-1253.5 h70
M10 Fab Notes:
  drawing of 173 lines, arcs and shapes, not listed
  text "DESIGN INFORMATION" at 12378.02,6211 h60
  text "MIN. TRACK WIDTH:" at 11733.46,6031 h60
  text "10" at 12829.7,6031 h60
  text "MIL" at 12984.46,6031 h60
  text "MIN. CLEARANCE:" at 11733.46,5899 h60
  text "0.2" at 12769.7,5899 h60
  text "mm" at 12984.46,5899 h60
  text "MIN. VIA PAD SIZE:" at 11733.46,5767 h60
  text "10" at 12799.71,5767 h60
  text "MIL" at 12984.46,5767 h60
  text "0.05mm (2MIL)" at 12428.46,5625.29 h60
  text "MINIMUM ANNULAR RING" at 11404.23,5621 h60
  text "EXTERNAL" at 13136.46,5621 h60
  text "PER" at 11604.23,5503 h60
  text "IPC-D-275 CLASS 2 LEVEL C" at 11824.23,5503 h60
  text "MIL, HOLES" at 13312.46,5390.71 h60
  text "+/-" at 12920,5390 h60
  text "+/-" at 13774,5390 h60
  text "REGISTRATION TOLERANCES:" at 11404.23,5385 h60
  text "METAL" at 12604,5385 h60
  text "5" at 13180.2,5385 h60
  text "3" at 14013.2,5385 h60
  text "MIL" at 14129.46,5385 h60
  text "+/-" at 13774,5272 h60
  text "HOLE SIZE TOLERANCE (UNLESS OTHERWISE SPECIFIED):" at 11404.23,5267 h60
  text "3" at 14013.2,5267 h60
  text "MIL" at 14129.46,5267 h60
  text "MATERIAL:" at 11329.46,5057.54 h60
  text "FR-4 High Tg" at 12315.9,4917.21 h60
  text "FR-408" at 11750.46,4908.64 h60
  text "OTHER" at 13238.46,4908.64 h60
  text "X" at 12161,4905 h60
  text "62 MIL (1.6mm) +/-10%" at 12070.56,4745.92 h60
  text "THICKNESS:" at 11404.23,4741.64 h60
  text "X" at 11942.4,4741.64 h60
  text "OTHER" at 13355.46,4741.64 h60
  text "TOLERANCE:" at 11404.23,4583.64 h60
  text "X" at 12243.53,4583.64 h60
  text "ANSI IPC-6012 TYPE 3 CLASS 2" at 12430.48,4583.64 h60
  text "OTHER +/-" at 12430.46,4427.64 h60
  text "BOW & TWIST:" at 11404.23,4270.64 h60
  text "X" at 12243.53,4270.64 h60
  text "ANSI IPC-6012 TYPE 3 CLASS 2" at 12430.48,4270.64 h60
  text "OTHER +/-" at 12430.46,4112.13 h60
  text "DRILLING:" at 11329.46,3973.64 h60
  text "REFERENCE:" at 11404.23,3856.64 h60
  text "X" at 12052.46,3856.64 h60
  text "AS SHOWN" at 12239.46,3856.64 h60
  text "X" at 12953.46,3856.64 h60
  text "NC_DRILL FILES" at 13090.46,3856.64 h60
  text "PTH COPPER THICKNESS:" at 11404.23,3698.64 h60
  text "X" at 12534.46,3698.64 h60
  text "20-30 um" at 12671.46,3698.64 h60
  text "OTHER" at 13388.46,3698.64 h60
  text "BOARD FINISH:" at 11329.46,3539.64 h60
  text "SILKSCREEN:" at 11484.68,3421.64 h60
  text "X" at 12433.46,3421.64 h60
  text "TOP" at 12559.46,3421.64 h60
  text "X" at 12943.46,3421.64 h60
  text "BOTTOM" at 13070.46,3421.64 h60
  text "SILKSCREEN COLOR:" at 11484.68,3254.64 h60
  text "X" at 12432.42,3254.64 h60
  text "WHITE" at 12559.46,3254.64 h60
  text "OTHER" at 13070.46,3254.64 h60
  text "X" at 12563.42,3095.44 h60
  text "GREEN" at 12690.46,3095.44 h60
  text "OTHER" at 13308.46,3095.44 h60
  text "SOLDER RESIST COLOR:" at 11484.68,3084.64 h60
  text "X" at 12563.42,2925.44 h60
  text "MATTE" at 12690.46,2925.44 h60
  text "SEMI-GLOSS" at 13308,2924.8 h60
  text "IMMERSION GOLD (ENIG)" at 12390.46,2736.92 h60
  text "ENEPIG" at 13728,2733.64 h60
  text "SURFACE FINISH:" at 11329.46,2732.64 h60
  text "IMM. TIN/SILVER OR EQUIV" at 11659,2575.64 h60
  text "OTHER" at 13090.46,2575.64 h60
  text "X" at 11495,2575 h60
  text "ARRAY/PANEL:" at 11329.46,2396.64 h60
  text "CUT AND TRIM PER M1 BOARD OUTLINE" at 12390.46,2392.35 h60
  text "N.C. ROUTE" at 12390.46,2240.64 h60
  text "X" at 13069.46,2240.64 h60
  text "V. SCORE" at 13256.46,2240.64 h60
  text "CERTIFICATION:" at 11329.46,2103.64 h60
  text "MATERIALS AND WORKMANSHIP FOR ALL PCBS" at 12054.46,2103.64 h60
  text "TO MEET OR EXCEED THE REQUIREMENTS OF:" at 12054.46,2005.64 h60
  text "X" at 11680.96,1869.13 h60
  text "ANSI IPC-A-600F CLASS ->" at 11819.96,1869.13 h60
  text "X" at 13459.02,1869.13 h60
  text "2" at 13577.96,1869.14 h60
  text "1" at 13262.96,1867.64 h60
  text "3" at 13931.96,1867.64 h60
  text "X" at 12495.02,1709.64 h60
  text "RoHS" at 12631.96,1709.64 h60
  text "OTHER" at 13276.36,1709.64 h60
  text "PER ORDER" at 13673.42,1709.64 h60
  text "ALL BOARDS MUST MEET OR EXCEED UL94-V0 REQUIREMENTS." at 11357,1544 h60
  text "PCB MUST BEAR THE UL94V-0 UL REGISTERED MATERIAL ID NUMBER" at 11357,1424 h60
  text "ADDITIONAL REQUIREMENTS:" at 11329.46,1250.64 h60
  text "MICROSECTION:" at 11404.23,1135.64 h60
  text "YES" at 12309.96,1135.64 h60
  text "REQUIRED" at 13171.46,979.49 h60
  text "BARE BOARD ELEC. TEST:" at 11404.23,976.64 h60
  text "NONE" at 12709.96,976.64 h60
  text "PER ORDER" at 13763.46,976.64 h60
  text "X" at 12585,975 h60
  text ".Layer_Name" at 577,-848.49 h60
M11 Gerber Information:
  lines w10: -292,-920.17 6308,-920.17 ; -292,-716.83 6310,-716.83 ; -292,-513.5 -292,-1123.5 3713,-1123.5 6310,-1123.5 6310,-513.5 -291.5,-513.5 -291.5,-1123.5 1284,-1123.5 ; 2173,-1123.5 2173,-513.5 ; 3440,-716.83 3440,-513.5 ; 4280,-716.83 4280,-513.5 ; 4902,-1130 4902,-927.17
  text "ALL ARTWORK VIEWED FROM TOP SIDE" at -228.5,-645.67 h60
  text "BOARD #:" at 2248,-645.67 h60
  text ".PRJ_Number" at 2793.5,-645.67 h60
  text "REV:" at 3638,-645.67 h60
  text ".PCB_Rev" at 3929.5,-645.67 h60
  text "SVN REV:" at 4476,-645.67 h60
  text ".VersionControl_RevNumber" at 4982,-645.67 h60
  text "LAYER NAME =" at -228.5,-848.49 h60
  text "TID #:" at 2248,-849 h60
  text ".TID" at 2793.5,-849 h60
  text "PLOT NAME =" at -228.5,-1054.34 h60
  text ".plot_File_Name" at 577,-1054.34 h60
  text "GENERATED    :" at 2250,-1054.34 h60
  text ".Print_Date" at 3119.5,-1054.34 h60
  text ".Print_Time" at 3848.5,-1054.34 h60
  text "TEXAS INSTRUMENTS" at 5113,-1054.34 h60
M12 Stackup:
  drawing of 191 lines, arcs and shapes, not listed
  text "Layer" at 9790.34,7840 h60
  text "Name" at 10200.26,7840 h60
  text "Material" at 11130,7840 h60
  text "Thickness" at 11989.77,7840 h60
  text "Constant" at 12639.6,7840 h60
  text "Board Layer Stack" at 13209.46,7840 h60
  text "1" at 9790.34,7720 h60
  text "Top Overlay" at 10200.26,7720 h60
  text "2" at 9790.34,7600 h60
  text "Top Solder" at 10200.26,7600 h60
  text "Solder Resist" at 11130,7600 h60
  text "0.40mil" at 11989.77,7600 h60
  text "3.5" at 12639.6,7600 h60
  text "3" at 9790.34,7480 h60
  text "Top Layer" at 10200.26,7480 h60
  text "Copper" at 11130,7480 h60
  text "1.40mil" at 11989.77,7480 h60
  text "4" at 9790.34,7360 h60
  text "Dielectric1" at 10200.26,7360 h60
  text "FR-4" at 11130,7360 h60
  text "59.20mil" at 11989.77,7360 h60
  text "4.8" at 12639.6,7360 h60
  text "5" at 9790.34,7240 h60
  text "Bottom Layer" at 10200.26,7240 h60
  text "Copper" at 11130,7240 h60
  text "1.40mil" at 11989.77,7240 h60
  text "6" at 9790.34,7120 h60
  text "Bottom Solder" at 10200.26,7120 h60
  text "Solder Resist" at 11130,7120 h60
  text "0.40mil" at 11989.77,7120 h60
  text "3.5" at 12639.6,7120 h60
  text "7" at 9790.34,7000 h60
  text "Bottom Overlay" at 10200.26,7000 h60
  text ".Layer_Name" at 577,-848.49 h60
M13 Component Bodies Top:
  text ".Layer_Name" at 577,-848.49 h60
M14 Component Bodies Bottom:
  text ".Layer_Name" at 577,-848.49 h60
M15 Courtyards Top:
  text ".Layer_Name" at 577,-848.49 h60
M16 Courtyards Bottom:
  text ".Layer_Name" at 577,-848.49 h60
Drill Drawing:
  circle w10: c5363.68,2779.36 r27.61
  lines w10: 5336.07,2931.23 5391.29,2931.23 5363.68,2876.01 5336.07,2931.23 ; 5336.07,3000.26 5391.29,3000.26 5391.29,3055.48 5336.07,3055.48 5336.07,3000.26 ; 5336.07,3138.32 5349.87,3138.32 5349.87,3124.51 5377.48,3124.51 5377.48,3138.32 5391.29,3138.32 5391.29,3165.93 5377.48,3165.93 5377.48,3179.74 5349.87,3179.74 5349.87,3165.93 5336.07,3165.93 5336.07,3138.32 ; 5336.07,3248.77 5363.68,3262.57 5391.29,3248.77 5377.48,3276.38 5391.29,3303.99 5363.68,3290.19 5336.07,3303.99 5349.87,3276.38 5336.07,3248.77
  lines w12: 5286,2714.48 8515.08,2714.48 ; 5286,3335.75 8515.08,3335.75 ; 5623.64,2590.22 5623.64,3460 ; 5955.48,2590.22 5955.48,3460 ; 6591.52,2590.22 6591.52,3460 ; 6850.47,2590.22 6850.47,3460 ; 7225.41,2590.22 7225.41,3460 ; 7948.98,2590.22 7948.98,3460 ; 5286,2590.22 8515.08,2590.22 8515.08,3460 5286,3460 5286,2590.22
  text "Symbol" at 5360.55,3373.02 h72
  text "Quantity" at 5660.92,3373.02 h72
  text "Finished Hole Size" at 5992.75,3373.02 h72
  text "Plated" at 6628.8,3373.02 h72
  text "Hole Type" at 6887.74,3373.02 h72
  text "Drill Layer Pair" at 7262.69,3373.02 h72
  text "Hole Tolerance" at 7986.26,3373.02 h72
  text "28" at 5660.92,3248.77 h60
  text "10.00mil (0.254mm)" at 5992.75,3248.77 h60
  text "PTH" at 6628.8,3248.77 h60
  text "Round" at 6887.74,3248.77 h60
  text "Top Layer - Bottom Layer" at 7262.69,3248.77 h60
  text "2" at 5660.92,3124.51 h60
  text "31.00mil (0.787mm)" at 5992.75,3124.51 h60
  text "PTH" at 6628.8,3124.51 h60
  text "Round" at 6887.74,3124.51 h60
  text "Top Layer - Bottom Layer" at 7262.69,3124.51 h60
  text "8" at 5660.92,3000.26 h60
  text "33.46mil (0.850mm)" at 5992.75,3000.26 h60
  text "PTH" at 6628.8,3000.26 h60
  text "Round" at 6887.74,3000.26 h60
  text "Top Layer - Bottom Layer" at 7262.69,3000.26 h60
  text "4" at 5660.92,2876.01 h60
  text "40.00mil (1.016mm)" at 5992.75,2876.01 h60
  text "PTH" at 6628.8,2876.01 h60
  text "Round" at 6887.74,2876.01 h60
  text "Top Layer - Bottom Layer" at 7262.69,2876.01 h60
  text "4" at 5660.92,2751.75 h60
  text "41.34mil (1.050mm)" at 5992.75,2751.75 h60
  text "PTH" at 6628.8,2751.75 h60
  text "Round" at 6887.74,2751.75 h60
  text "Top Layer - Bottom Layer" at 7262.69,2751.75 h60
  text "46 Total" at 5660.92,2627.5 h60
  text ".Layer_Name" at 577,-848.49 h60
M17 Embedded Cavity:
  text ".Layer_Name" at 577,-848.49 h60
M18 Embedded Assembly:
  text ".Layer_Name" at 577,-848.49 h60
M19 Embedded Keepout:
  text ".Layer_Name" at 577,-848.49 h60

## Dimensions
0,0 to 0,1600 on M2 Board Dimensions
0,-390 to 1000,-390 on M2 Board Dimensions
0,10 to 2960,0 on M2 Board Dimensions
